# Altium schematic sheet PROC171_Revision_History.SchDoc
size 431 x 279 mm; Date: Not shown in title block; ApprovedBy: Not shown in title block; CheckedBy: Not shown in title block; Author: Not shown in title block; CompanyName: Not shown in title block; Engineer: Shrinivas/Rakesh; Organization: Not shown in title block; Address1: Not shown in title block; Address2: Not shown in title block; Address3: Not shown in title block; Address4: Not shown in title block; DocumentNumber: 2; Rev: A; SheetNumber: 2; SheetTotal: 27; PageSetup: Record=PageOptions¦CenterHorizontal=True¦CenterVertical=True¦PrintScale=1.00¦XCorrection=1.00¦YCorrection=1.00¦PrintKind=0¦BorderSize=5000000¦LeftOffset=0¦BottomOffset=0¦Orientation=2¦PaperLength=1000¦PaperWidth=1000¦Scale=100¦PaperSource=15¦PrintQuality=600¦MediaType=1¦DitherType=10¦PaperKind=Letter¦PrintScaleMode=1; Revision: E1
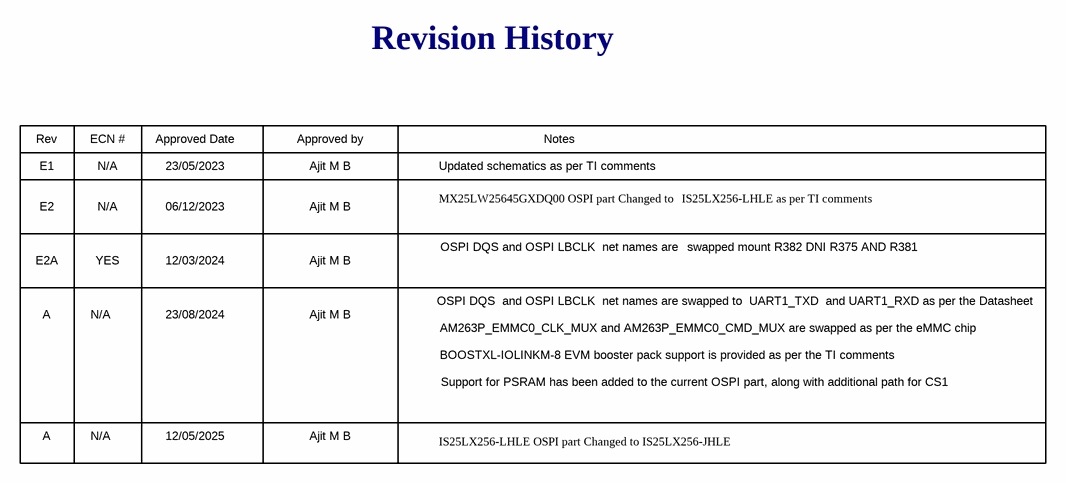
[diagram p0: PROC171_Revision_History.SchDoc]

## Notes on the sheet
- Revision History
- Rev
- ECN #
- Approved Date
- Approved by
- Notes
- E1
- E2
- N/A
- 23/05/2023
- 06/12/2023
- Ajit M B
- Updated schematics as per TI comments
- MX25LW25645GXDQ00 OSPI part Changed to
- IS25LX256-LHLE as per TI comments
- E2A
- YES
- 12/03/2024
- OSPI DQS and OSPI LBCLK  net names are
- swapped mount R382 DNI R375 AND R381
- A
- 23/08/2024
- BOOSTXL-IOLINKM-8 EVM booster pack support is provided as per the TI comments
- AM263P_EMMC0_CLK_MUX and AM263P_EMMC0_CMD_MUX are swapped as per the eMMC chip
- OSPI DQS  and OSPI LBCLK  net names are swapped to  UART1_TXD  and UART1_RXD as per the Datasheet
- Support for PSRAM has been added to the current OSPI part, along with additional path for CS1
- 12/05/2025
- IS25LX256-LHLE OSPI part Changed to IS25LX256-JHLE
